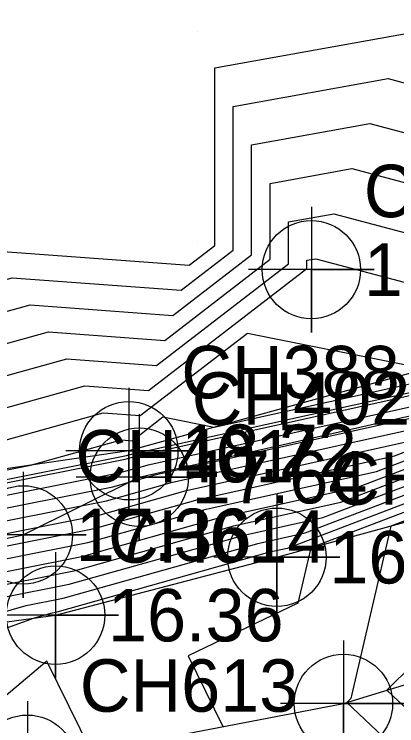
# Model space of a CAD drawing. Extents: x 2531902 to 2533249, y 715219 to 716099.
# Drawn here: x 2532801.29 to 2532819.51, y 715636.9 to 715670.81 of the extents above; entities that cross this region are included whole.
import ezdxf

# ---------------------------------------------------------------- set-up
doc = ezdxf.new("R2010")
doc.units = 0
for name, color, linetype in [('DTM Contours Major', 7, 'Continuous'), ('DTM Contours Minor', 7, 'Continuous'), ('Exist DTM Breakline', 7, 'Continuous'), ('Exist DTM Breakline Cogo Elevation', 7, 'Continuous'), ('Exist DTM Breakline Cogo Number', 7, 'Continuous'), ('Exist DTM Breakline Cogo Point CELL', 7, 'Continuous'), ('Exist DTM Breakline Underwater', 7, 'Continuous'), ('Exist DTM Breakline Underwater Cogo Elevation', 7, 'Continuous'), ('Exist DTM Breakline Underwater Cogo Number', 7, 'Continuous'), ('Exist DTM Breakline Underwater Cogo Point CELL', 7, 'Continuous'), ('Exist DTM Drainline', 7, 'Continuous'), ('Exist DTM Drainline Cogo Number', 7, 'Continuous'), ('Exist DTM Drainline Cogo Point CELL', 7, 'Continuous'), ('Exist DTM QL2 LIDAR Elevation Point', 7, 'Continuous'), ('Exist DTM Regular Point CELL', 7, 'Continuous'), ('Exist DTM Regular Point Cogo Elevation', 7, 'Continuous'), ('Exist DTM Regular Point Cogo Number', 7, 'Continuous'), ('Exist Hydro Stream or Body of Water', 7, 'Continuous'), ('Scratch_Level_2', 7, 'Continuous')]:
    doc.layers.add(name, color=color, linetype=linetype)

msp = doc.modelspace()

# ---------------------------------------------------------------- linework, layer by layer
at = {"layer": 'DTM Contours Major'}
for points in [[(2532787.963, 715647.113), (2532788.11, 715647.155), (2532790.468, 715647.623), (2532805.524, 715651.812), (2532807.289, 715651.681), (2532812.395, 715655.613), (2532820.905, 715653.907), (2532825.351, 715654.892), (2532826.014, 715655.145), (2532830.295, 715655.728), (2532841.623, 715657.272), (2532847.51, 715658.105), (2532847.908, 715661.158), (2532847.985, 715662.951), (2532851.196, 715670.232), (2532853.299, 715672.201), (2532858.259, 715675.616), (2532855.007, 715669.369), (2532850.728, 715661.954), (2532851.349, 715661.97)], [(2532742.632, 715654.879), (2532744.549, 715654.106), (2532746.734, 715656.99), (2532751.645, 715657.927), (2532759.371, 715659.033), (2532766.385, 715658.274), (2532769.514, 715656.994), (2532772.06, 715658.012), (2532779.096, 715657.172), (2532786.334, 715657.813), (2532789.538, 715657.253), (2532797.31, 715657.175), (2532801.18, 715658.251), (2532809.235, 715657.654), (2532811.722, 715659.569), (2532811.717, 715666.416), (2532819.095, 715667.743), (2532821.087, 715667.214), (2532829.089, 715659.21)], [(2532789.628, 715644.057), (2532793.839, 715645.27), (2532805.68, 715647.62), (2532808.608, 715648.444), (2532808.828, 715648.506), (2532821.098, 715651.224), (2532826.139, 715653.145), (2532828.649, 715654.101), (2532844.867, 715656.311), (2532846.614, 715656.538), (2532851.45, 715657.166), (2532860.686, 715660.385), (2532865.301, 715655.109), (2532866.396, 715654.713), (2532867.485, 715654.419), (2532869.624, 715653.149), (2532880.592, 715648.052), (2532883.273, 715646.806)], [(2532786.783, 715639.599), (2532788.186, 715640.107), (2532799.568, 715643.384), (2532804.204, 715644.304), (2532811.635, 715646.396), (2532811.727, 715646.422), (2532816.845, 715647.556), (2532829.641, 715652.432), (2532831.284, 715653.058), (2532841.899, 715654.505), (2532843.043, 715654.653), (2532855.32, 715656.247), (2532862.023, 715658.583), (2532865.372, 715654.754), (2532866.166, 715654.467), (2532866.956, 715654.253), (2532868.509, 715653.332), (2532876.468, 715649.633), (2532880.776, 715647.631)], [(2532842.838, 715653.205), (2532839.472, 715652.768), (2532838.932, 715652.698), (2532833.919, 715652.015), (2532833.143, 715651.719), (2532819.223, 715646.415), (2532817.319, 715638.198), (2532817.128, 715638.01), (2532821.44, 715633.942)]]:
    msp.add_lwpolyline(points, dxfattribs=at)
at = {"layer": 'DTM Contours Minor'}
for points in [[(2532800.311, 715659.539), (2532809.625, 715658.849), (2532810.845, 715659.788), (2532810.839, 715668.249), (2532819.955, 715669.889), (2532820.053, 715669.863), (2532829.959, 715659.954), (2532838.836, 715659.611), (2532840.568, 715659.857), (2532840.598, 715660.088), (2532840.988, 715669.128), (2532841.385, 715670.029), (2532850.579, 715678.632)], [(2532795.329, 715655.094), (2532802.048, 715656.963), (2532808.846, 715656.459), (2532812.598, 715659.349), (2532812.594, 715664.583), (2532818.234, 715665.597), (2532822.121, 715664.566), (2532828.438, 715658.248), (2532834.098, 715658.029), (2532842.882, 715659.273), (2532843.035, 715660.444)], [(2532793.348, 715653.013), (2532802.917, 715655.675), (2532808.457, 715655.265), (2532813.475, 715659.13), (2532813.472, 715662.75), (2532817.373, 715663.451), (2532823.155, 715661.917), (2532827.677, 715657.394), (2532831.728, 715657.238), (2532844.039, 715658.981)], [(2532791.367, 715650.933), (2532803.786, 715654.387), (2532808.067, 715654.07), (2532814.352, 715658.91), (2532814.35, 715660.916), (2532816.512, 715661.305), (2532824.189, 715659.268), (2532826.916, 715656.541), (2532829.359, 715656.447), (2532845.196, 715658.689)], [(2532789.386, 715648.852), (2532804.655, 715653.1), (2532807.678, 715652.875), (2532815.229, 715658.69), (2532815.228, 715659.083), (2532815.652, 715659.16), (2532825.223, 715656.62), (2532826.155, 715655.688), (2532826.99, 715655.656), (2532846.353, 715658.397)], [(2532789.256, 715646.778), (2532802.068, 715649.321), (2532806.392, 715650.524), (2532806.899, 715650.486), (2532808.366, 715651.616), (2532810.81, 715651.126), (2532824.5, 715654.158), (2532826.541, 715654.936), (2532839.724, 715656.732), (2532847.24, 715657.757)], [(2532900.102, 715635.723), (2532888.893, 715641.875), (2532885.96, 715644.721), (2532885.74, 715644.876), (2532884.67, 715645.619), (2532873.994, 715650.581), (2532867.84, 715653.441), (2532866.639, 715654.154), (2532866.028, 715654.319), (2532865.414, 715654.541), (2532862.824, 715657.502), (2532857.642, 715655.695), (2532840.901, 715653.522), (2532840.119, 715653.421), (2532832.865, 715652.432), (2532831.742, 715652.004), (2532814.293, 715645.355), (2532813.467, 715645.172), (2532813.452, 715645.167), (2532803.318, 715642.315), (2532803.006, 715642.253), (2532802.238, 715642.032), (2532782.087, 715634.737)], [(2532790.402, 715646.401), (2532806.566, 715649.609), (2532806.791, 715649.672), (2532807.089, 715649.756), (2532823.65, 715653.425), (2532824.037, 715653.573), (2532827.068, 715654.727), (2532846.647, 715657.395)], [(2532791.548, 715646.024), (2532806.271, 715648.946), (2532807.397, 715649.263), (2532807.668, 715649.339), (2532822.799, 715652.691), (2532824.738, 715653.43), (2532827.595, 715654.519), (2532846.054, 715657.034)], [(2532901.681, 715634.486), (2532888.729, 715641.594), (2532886.177, 715644.071), (2532885.601, 715644.475), (2532882.802, 715646.42), (2532873.17, 715650.897), (2532867.617, 715653.478), (2532866.534, 715654.121), (2532865.982, 715654.269), (2532865.428, 715654.47), (2532863.092, 715657.141), (2532858.416, 715655.511), (2532840.186, 715653.145), (2532839.525, 715653.059), (2532833.392, 715652.224), (2532832.442, 715651.862), (2532815.412, 715645.372), (2532814.8, 715642.735), (2532809.568, 715640.234), (2532811.222, 715636.857)], [(2532792.694, 715645.647), (2532805.976, 715648.283), (2532808.002, 715648.853), (2532808.248, 715648.922), (2532821.948, 715651.958), (2532825.438, 715653.287), (2532828.122, 715654.31), (2532845.46, 715656.673)], [(2532904.838, 715632.011), (2532888.401, 715641.032), (2532886.611, 715642.77), (2532885.323, 715643.673), (2532879.065, 715648.023), (2532871.52, 715651.529), (2532867.171, 715653.551), (2532866.322, 715654.054), (2532865.89, 715654.171), (2532865.456, 715654.328), (2532863.626, 715656.42), (2532859.964, 715655.144), (2532838.758, 715652.391), (2532838.339, 715652.337), (2532834.446, 715651.806), (2532833.843, 715651.577), (2532823.034, 715647.458), (2532821.555, 715641.078), (2532819.036, 715638.593), (2532825.049, 715632.922)], [(2532800.714, 715643.007), (2532803.909, 715643.641), (2532812.241, 715645.987), (2532812.307, 715646.005), (2532815.994, 715646.822), (2532830.341, 715652.289), (2532831.811, 715652.849), (2532841.306, 715654.143), (2532842.329, 715654.276), (2532856.094, 715656.063)], [(2532794.985, 715644.893), (2532805.385, 715646.956), (2532809.213, 715648.034), (2532809.408, 715648.089), (2532820.247, 715650.49), (2532826.839, 715653.002), (2532829.176, 715653.893), (2532844.273, 715655.95)], [(2532797.554, 715641.39), (2532801.86, 715642.63), (2532803.614, 715642.978), (2532812.846, 715645.577), (2532812.887, 715645.588), (2532815.143, 715646.088), (2532831.041, 715652.147), (2532832.338, 715652.641), (2532840.712, 715653.782), (2532841.615, 715653.899), (2532856.868, 715655.879)], [(2532796.131, 715644.515), (2532805.09, 715646.293), (2532809.819, 715647.625), (2532809.988, 715647.672), (2532819.396, 715649.757), (2532827.539, 715652.86), (2532829.703, 715653.684), (2532843.68, 715655.589)], [(2532797.277, 715644.138), (2532804.795, 715645.63), (2532810.424, 715647.215), (2532810.568, 715647.255), (2532818.546, 715649.023), (2532828.24, 715652.717), (2532830.23, 715653.475), (2532843.086, 715655.227)], [(2532798.422, 715643.761), (2532804.499, 715644.967), (2532811.03, 715646.806), (2532811.147, 715646.839), (2532817.695, 715648.289), (2532828.94, 715652.575), (2532830.757, 715653.267), (2532842.493, 715654.866), (2532843.757, 715655.03)], [(2532806.116, 715634.45), (2532804.96, 715635.654), (2532802.84, 715639.981), (2532796.403, 715634.562), (2532799.88, 715631.408), (2532806.116, 715634.45)]]:
    msp.add_lwpolyline(points, dxfattribs=at)
at = {"layer": 'Exist DTM Breakline'}
msp.add_lwpolyline([(2532863.072, 715660.678), (2532859.426, 715662.085), (2532849.717, 715661.422), (2532847.724, 715658.051), (2532825.76, 715655.245), (2532806.743, 715650.005), (2532787.852, 715647.24), (2532777.892, 715646.595), (2532766.74, 715639.821), (2532753.665, 715642.294), (2532729.328, 715651.531), (2532716.286, 715652.801)], dxfattribs=at)
at = {"layer": 'Exist DTM Breakline Cogo Point CELL'}
for points in [[(2532806.743, 715653.005), (2532806.743, 715647.005), (2532806.743, 715650.005), (2532809.743, 715650.005), (2532803.743, 715650.005)], [(2532806.743, 715653.005), (2532806.743, 715647.005), (2532806.743, 715650.005), (2532809.743, 715650.005), (2532803.743, 715650.005)], [(2532807.244, 715651.747), (2532807.244, 715645.747), (2532807.244, 715648.747), (2532810.244, 715648.747), (2532804.244, 715648.747)], [(2532801.718, 715648.997), (2532801.718, 715642.997), (2532801.718, 715645.997), (2532804.718, 715645.997), (2532798.718, 715645.997)]]:
    msp.add_lwpolyline(points, dxfattribs=at)
for centre in [(2532806.743, 715650.005), (2532806.743, 715650.005), (2532807.244, 715648.747), (2532801.718, 715645.997)]:
    msp.add_circle(centre, 2.344, dxfattribs=at)
at = {"layer": 'Exist DTM Breakline Underwater'}
msp.add_lwpolyline([(2532646.748, 715755.182), (2532668.676, 715717.147), (2532677.241, 715702.567), (2532689.842, 715666.582), (2532701.723, 715652.924), (2532713.134, 715647.155), (2532737.59, 715643.253), (2532756.176, 715636.457), (2532783.406, 715639.452), (2532803.254, 715642.171), (2532813.801, 715644.931), (2532836.277, 715651.081), (2532865.559, 715653.815), (2532885.826, 715645.124), (2532889.946, 715643.683), (2532906.865, 715630.423), (2532927.34, 715618.228), (2532957.965, 715607.729), (2532978.566, 715598.571), (2533001.091, 715586.568), (2533028.19, 715572.821)], dxfattribs=at)
at = {"layer": 'Exist DTM Breakline Underwater Cogo Point CELL'}
for points in [[(2532813.801, 715647.931), (2532813.801, 715641.931), (2532813.801, 715644.931), (2532816.801, 715644.931), (2532810.801, 715644.931)], [(2532803.254, 715645.171), (2532803.254, 715639.171), (2532803.254, 715642.171), (2532806.254, 715642.171), (2532800.254, 715642.171)]]:
    msp.add_lwpolyline(points, dxfattribs=at)
for centre in [(2532813.801, 715644.931), (2532803.254, 715642.171)]:
    msp.add_circle(centre, 2.344, dxfattribs=at)
at = {"layer": 'Exist DTM Drainline'}
msp.add_lwpolyline([(2532712.089, 715642.317), (2532734.218, 715637.287), (2532753.576, 715632.211), (2532781.659, 715633.208), (2532801.91, 715635.068), (2532816.971, 715637.962), (2532839.573, 715644.872), (2532859.48, 715643.736), (2532879.315, 715631.66), (2532904.837, 715623.619), (2532925.407, 715612.713), (2532951.291, 715602.124), (2532975.159, 715591.05), (2532999.274, 715579.213), (2533023.429, 715565.909)], dxfattribs=at)
at = {"layer": 'Exist DTM Drainline Cogo Point CELL'}
for points in [[(2532816.971, 715640.962), (2532816.971, 715634.962), (2532816.971, 715637.962), (2532819.971, 715637.962), (2532813.971, 715637.962)], [(2532801.91, 715638.068), (2532801.91, 715632.068), (2532801.91, 715635.068), (2532804.91, 715635.068), (2532798.91, 715635.068)]]:
    msp.add_lwpolyline(points, dxfattribs=at)
for centre in [(2532816.971, 715637.962), (2532801.91, 715635.068)]:
    msp.add_circle(centre, 2.344, dxfattribs=at)
at = {"layer": 'Exist DTM QL2 LIDAR Elevation Point'}
for p, q in [((2532810, 715670), (2532810, 715670)), ((2532810, 715660), (2532810, 715660))]:
    msp.add_line(p, q, dxfattribs=at)
at = {"layer": 'Exist DTM Regular Point CELL'}
msp.add_lwpolyline([(2532815.442, 715661.637), (2532815.442, 715655.637), (2532815.442, 715658.637), (2532818.442, 715658.637), (2532812.442, 715658.637)], dxfattribs=at)
msp.add_circle((2532815.442, 715658.637), 2.344, dxfattribs=at)
at = {"layer": 'Exist Hydro Stream or Body of Water'}
msp.add_lwpolyline([(2532790.115, 715646.495), (2532806.64, 715649.775), (2532806.944, 715649.86), (2532823.862, 715653.608), (2532826.936, 715654.78), (2532846.795, 715657.486), (2532848.935, 715657.763), (2532859.818, 715661.557), (2532865.255, 715655.34), (2532866.545, 715654.873), (2532867.828, 715654.527), (2532870.349, 715653.031), (2532883.272, 715647.025), (2532884.83, 715646.372), (2532885.882, 715645.762), (2532886.539, 715645.426), (2532889.693, 715644.068), (2532889.952, 715644.137), (2532891.522, 715643.982), (2532891.782, 715643.826), (2532896.496, 715640.921), (2532907.078, 715634.646)], dxfattribs=at)
at = {"layer": 'Scratch_Level_2'}
msp.add_lwpolyline([(2532714.118, 715649.677), (2532729.178, 715648.995), (2532753.386, 715638.683), (2532767.656, 715638.089), (2532777.579, 715641.803), (2532788.373, 715643.181), (2532801.718, 715645.997), (2532807.244, 715648.747), (2532822.52, 715652.218), (2532826.019, 715654.258), (2532837.833, 715654.827), (2532847.619, 715656.074), (2532850.366, 715659.741), (2532854.722, 715660.175), (2532860.554, 715659.882), (2532861.668, 715659.678), (2532862.953, 715658.263)], dxfattribs=at)

# ---------------------------------------------------------------- texts
at = {"layer": 'Exist DTM Breakline Cogo Elevation'}
for s, p in [('18.22', (2532809.243, 715648.755)), ('18.72', (2532809.243, 715648.755)), ('17.64', (2532809.744, 715647.497)), ('17.36', (2532804.218, 715644.747))]:
    msp.add_text(s, height=2.5, dxfattribs=at).set_placement(p)
at = {"layer": 'Exist DTM Breakline Cogo Number'}
for s, p in [('CH388', (2532809.243, 715652.505)), ('CH388', (2532809.243, 715652.505)), ('CH402', (2532809.744, 715651.247)), ('CH401', (2532804.218, 715648.497))]:
    msp.add_text(s, height=2.5, dxfattribs=at).set_placement(p)
at = {"layer": 'Exist DTM Breakline Underwater Cogo Elevation'}
for s, p in [('16.28', (2532816.301, 715643.681)), ('16.36', (2532805.754, 715640.921))]:
    msp.add_text(s, height=2.5, dxfattribs=at).set_placement(p)
at = {"layer": 'Exist DTM Breakline Underwater Cogo Number'}
for s, p in [('CH615', (2532816.301, 715647.431)), ('CH614', (2532805.754, 715644.671))]:
    msp.add_text(s, height=2.5, dxfattribs=at).set_placement(p)
at = {"layer": 'Exist DTM Drainline Cogo Number'}
msp.add_text('CH613', height=2.5, dxfattribs=at).set_placement((2532804.41, 715637.568))
at = {"layer": 'Exist DTM Regular Point Cogo Elevation'}
msp.add_text('19.15', height=2.5, dxfattribs=at).set_placement((2532817.942, 715657.387))
at = {"layer": 'Exist DTM Regular Point Cogo Number'}
msp.add_text('CH420', height=2.5, dxfattribs=at).set_placement((2532817.942, 715661.137))

doc.saveas('drawing.dxf')
